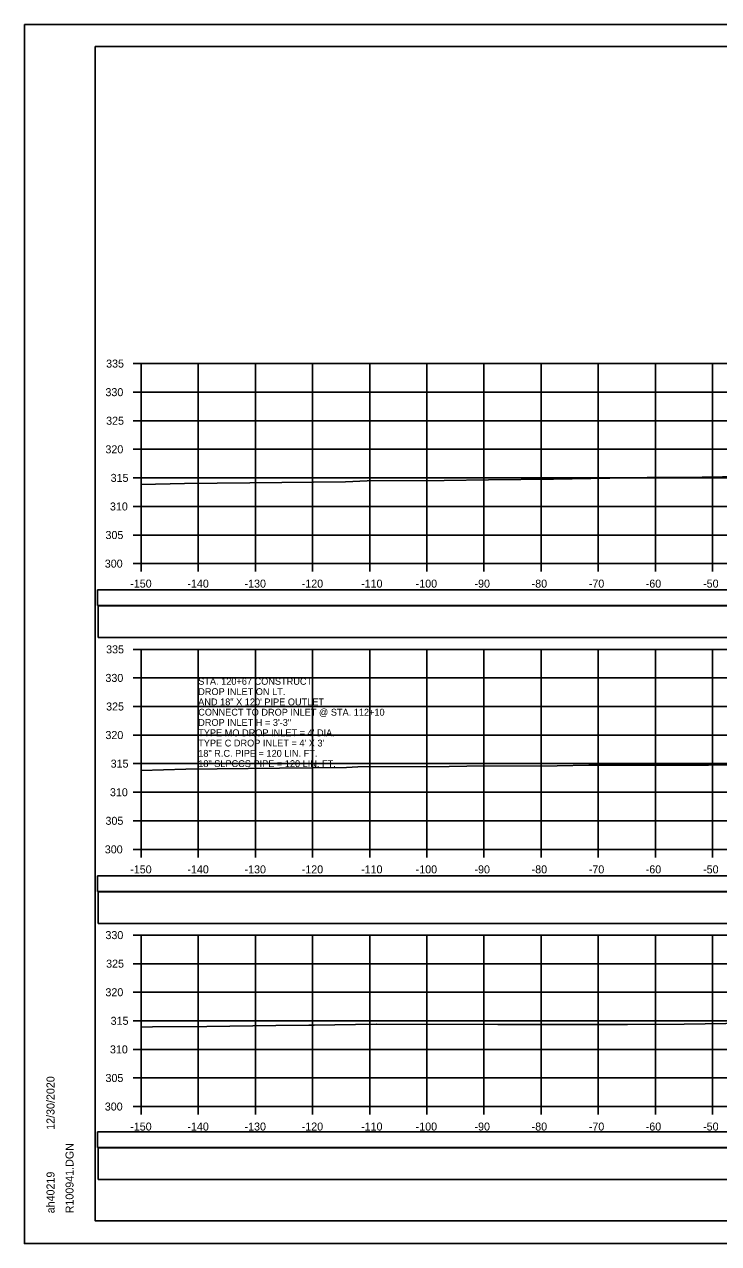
# Model space of a CAD drawing. Extents: x 1370538 to 1372872, y 376220 to 381127.
# Drawn here: x 1371871.6 to 1371993, y 380258.4 to 380471.7 of the extents above; entities that cross this region are included whole.
import ezdxf

# ---------------------------------------------------------------- set-up
doc = ezdxf.new("R2010")
doc.units = 0
for name, color, linetype in [('R_Border Notes', 7, 'Continuous'), ('R_Border PE', 7, 'Continuous'), ('R_Border Prem', 7, 'Continuous'), ('R_Dimension', 7, 'Continuous'), ('R_Fin Surface', 7, 'Continuous'), ('R_Grid', 7, 'Continuous'), ('R_No Plot', 7, 'Continuous'), ('R_Water Annot', 7, 'Continuous'), ('T_Detection Zones', 7, 'Continuous')]:
    doc.layers.add(name, color=color, linetype=linetype)

msp = doc.modelspace()

# ---------------------------------------------------------------- linework, layer by layer
at = {"layer": 'R_Border Notes'}
for p, q in [((1371883.97, 380467.83), (1372200.15, 380467.83)), ((1371883.97, 380262.37), (1371883.97, 380467.83)), ((1371883.97, 380262.37), (1371883.97, 380262.37)), ((1372200.15, 380262.37), (1371883.97, 380262.37))]:
    msp.add_line(p, q, dxfattribs=at)
at = {"layer": 'R_Border Prem'}
for p, q in [((1371890.57, 380412.37), (1371891.97, 380412.37)), ((1371891.97, 380377.37), (1371891.97, 380412.37)), ((1371890.57, 380407.37), (1371891.97, 380407.37)), ((1371890.57, 380402.37), (1371891.97, 380402.37)), ((1371890.57, 380397.37), (1371891.97, 380397.37)), ((1371890.57, 380392.37), (1371891.97, 380392.37)), ((1371890.57, 380387.37), (1371891.97, 380387.37)), ((1371890.57, 380382.37), (1371891.97, 380382.37)), ((1371890.57, 380377.37), (1371891.97, 380377.37)), ((1371891.97, 380377.37), (1372191.97, 380377.37)), ((1371891.97, 380375.97), (1371891.97, 380377.37)), ((1371901.97, 380375.97), (1371901.97, 380377.37)), ((1371911.97, 380375.97), (1371911.97, 380377.37)), ((1371921.97, 380375.97), (1371921.97, 380377.37)), ((1371931.97, 380375.97), (1371931.97, 380377.37)), ((1371941.97, 380375.97), (1371941.97, 380377.37)), ((1371951.97, 380375.97), (1371951.97, 380377.37)), ((1371961.97, 380375.97), (1371961.97, 380377.37)), ((1371971.97, 380375.97), (1371971.97, 380377.37)), ((1371981.97, 380375.97), (1371981.97, 380377.37)), ((1371991.97, 380375.97), (1371991.97, 380377.37)), ((1371890.57, 380362.37), (1371891.97, 380362.37)), ((1371891.97, 380327.37), (1371891.97, 380362.37)), ((1371890.57, 380357.37), (1371891.97, 380357.37)), ((1371890.57, 380352.37), (1371891.97, 380352.37)), ((1371890.57, 380347.37), (1371891.97, 380347.37)), ((1371890.57, 380342.37), (1371891.97, 380342.37)), ((1371890.57, 380337.37), (1371891.97, 380337.37)), ((1371890.57, 380332.37), (1371891.97, 380332.37)), ((1371890.57, 380327.37), (1371891.97, 380327.37)), ((1371891.97, 380327.37), (1372191.97, 380327.37)), ((1371891.97, 380325.97), (1371891.97, 380327.37)), ((1371901.97, 380325.97), (1371901.97, 380327.37)), ((1371911.97, 380325.97), (1371911.97, 380327.37)), ((1371921.97, 380325.97), (1371921.97, 380327.37)), ((1371931.97, 380325.97), (1371931.97, 380327.37)), ((1371941.97, 380325.97), (1371941.97, 380327.37)), ((1371951.97, 380325.97), (1371951.97, 380327.37)), ((1371961.97, 380325.97), (1371961.97, 380327.37)), ((1371971.97, 380325.97), (1371971.97, 380327.37)), ((1371981.97, 380325.97), (1371981.97, 380327.37)), ((1371991.97, 380325.97), (1371991.97, 380327.37)), ((1371890.57, 380312.37), (1371891.97, 380312.37)), ((1371891.97, 380282.37), (1371891.97, 380312.37)), ((1371890.57, 380307.37), (1371891.97, 380307.37)), ((1371890.57, 380302.37), (1371891.97, 380302.37)), ((1371890.57, 380297.37), (1371891.97, 380297.37)), ((1371890.57, 380292.37), (1371891.97, 380292.37)), ((1371890.57, 380287.37), (1371891.97, 380287.37)), ((1371890.57, 380282.37), (1371891.97, 380282.37)), ((1371891.97, 380282.37), (1372191.97, 380282.37)), ((1371891.97, 380280.97), (1371891.97, 380282.37)), ((1371901.97, 380280.97), (1371901.97, 380282.37)), ((1371911.97, 380280.97), (1371911.97, 380282.37)), ((1371921.97, 380280.97), (1371921.97, 380282.37)), ((1371931.97, 380280.97), (1371931.97, 380282.37)), ((1371941.97, 380280.97), (1371941.97, 380282.37)), ((1371951.97, 380280.97), (1371951.97, 380282.37)), ((1371961.97, 380280.97), (1371961.97, 380282.37)), ((1371971.97, 380280.97), (1371971.97, 380282.37)), ((1371981.97, 380280.97), (1371981.97, 380282.37)), ((1371991.97, 380280.97), (1371991.97, 380282.37))]:
    msp.add_line(p, q, dxfattribs=at)
at = {"layer": 'R_Dimension'}
for points in [[(1371891.97, 380391.19), (1371899.58, 380391.4), (1371911.02, 380391.52), (1371927.76, 380391.7), (1371931.54, 380391.84), (1371945.03, 380391.91), (1371952.77, 380392.04), (1371964.11, 380392.12), (1371980.5, 380392.43), (1371985.29, 380392.43), (1371986.59, 380392.43), (1372000.75, 380392.65)], [(1371891.97, 380341.19), (1371899.79, 380341.41), (1371916.18, 380341.58), (1371927.92, 380341.72), (1371929.91, 380341.79), (1371945.86, 380341.86), (1371948.97, 380341.91), (1371964.78, 380341.99), (1371970.33, 380342.08), (1371979.56, 380342.1), (1371986.59, 380342.11), (1371991.28, 380342.11), (1371995.62, 380342.19)], [(1371891.97, 380296.27), (1371893.95, 380296.33), (1371903.47, 380296.39), (1371915.55, 380296.54), (1371921.3, 380296.61), (1371922.24, 380296.61), (1371933.1, 380296.76), (1371933.12, 380296.76), (1371933.16, 380296.76), (1371954.4, 380296.75), (1371963.68, 380296.73), (1371970.39, 380296.75), (1371977.1, 380296.75), (1371987.01, 380296.78), (1372005.27, 380297.05)]]:
    msp.add_lwpolyline(points, dxfattribs=at)
at = {"layer": 'R_Fin Surface'}
for points in [[(1371884.44, 380364.44), (1372199.45, 380364.44), (1372199.45, 380370), (1371884.44, 380370)], [(1371884.44, 380314.39), (1372199.45, 380314.39), (1372199.45, 380319.95), (1371884.44, 380319.95)], [(1371884.44, 380269.6), (1372199.45, 380269.6), (1372199.45, 380275.17), (1371884.44, 380275.17)]]:
    msp.add_lwpolyline(points, close=True, dxfattribs=at)
at = {"layer": 'R_Grid'}
for p, q in [((1371891.97, 380412.37), (1372191.97, 380412.37)), ((1371891.97, 380377.37), (1371891.97, 380412.37)), ((1371901.97, 380377.37), (1371901.97, 380412.37)), ((1371911.97, 380377.37), (1371911.97, 380412.37)), ((1371921.97, 380377.37), (1371921.97, 380412.37)), ((1371931.97, 380377.37), (1371931.97, 380412.37)), ((1371941.97, 380377.37), (1371941.97, 380412.37)), ((1371951.97, 380377.37), (1371951.97, 380412.37)), ((1371961.97, 380377.37), (1371961.97, 380412.37)), ((1371971.97, 380377.37), (1371971.97, 380412.37)), ((1371981.97, 380377.37), (1371981.97, 380412.37)), ((1371991.97, 380377.37), (1371991.97, 380412.37)), ((1371891.97, 380407.37), (1372191.97, 380407.37)), ((1371891.97, 380402.37), (1372191.97, 380402.37)), ((1371891.97, 380397.37), (1372191.97, 380397.37)), ((1371891.97, 380392.37), (1372191.97, 380392.37)), ((1371891.97, 380387.37), (1372191.97, 380387.37)), ((1371891.97, 380382.37), (1372191.97, 380382.37)), ((1371891.97, 380377.37), (1372191.97, 380377.37)), ((1371891.97, 380362.37), (1372191.97, 380362.37)), ((1371891.97, 380327.37), (1371891.97, 380362.37)), ((1371901.97, 380327.37), (1371901.97, 380362.37)), ((1371911.97, 380327.37), (1371911.97, 380362.37)), ((1371921.97, 380327.37), (1371921.97, 380362.37)), ((1371931.97, 380327.37), (1371931.97, 380362.37)), ((1371941.97, 380327.37), (1371941.97, 380362.37)), ((1371951.97, 380327.37), (1371951.97, 380362.37)), ((1371961.97, 380327.37), (1371961.97, 380362.37)), ((1371971.97, 380327.37), (1371971.97, 380362.37)), ((1371981.97, 380327.37), (1371981.97, 380362.37)), ((1371991.97, 380327.37), (1371991.97, 380362.37)), ((1371891.97, 380357.37), (1372191.97, 380357.37)), ((1371891.97, 380352.37), (1372191.97, 380352.37)), ((1371891.97, 380347.37), (1372191.97, 380347.37)), ((1371891.97, 380342.37), (1372191.97, 380342.37)), ((1371891.97, 380337.37), (1372191.97, 380337.37)), ((1371891.97, 380332.37), (1372191.97, 380332.37)), ((1371891.97, 380327.37), (1372191.97, 380327.37)), ((1371891.97, 380312.37), (1372191.97, 380312.37)), ((1371891.97, 380282.37), (1371891.97, 380312.37)), ((1371901.97, 380282.37), (1371901.97, 380312.37)), ((1371911.97, 380282.37), (1371911.97, 380312.37)), ((1371921.97, 380282.37), (1371921.97, 380312.37)), ((1371931.97, 380282.37), (1371931.97, 380312.37)), ((1371941.97, 380282.37), (1371941.97, 380312.37)), ((1371951.97, 380282.37), (1371951.97, 380312.37)), ((1371961.97, 380282.37), (1371961.97, 380312.37)), ((1371971.97, 380282.37), (1371971.97, 380312.37)), ((1371981.97, 380282.37), (1371981.97, 380312.37)), ((1371991.97, 380282.37), (1371991.97, 380312.37)), ((1371891.97, 380307.37), (1372191.97, 380307.37)), ((1371891.97, 380302.37), (1372191.97, 380302.37)), ((1371891.97, 380297.37), (1372191.97, 380297.37)), ((1371891.97, 380292.37), (1372191.97, 380292.37)), ((1371891.97, 380287.37), (1372191.97, 380287.37)), ((1371891.97, 380282.37), (1372191.97, 380282.37))]:
    msp.add_line(p, q, dxfattribs=at)
at = {"layer": 'R_No Plot'}
for p, q in [((1371871.57, 380471.72), (1372204.9, 380471.72)), ((1371871.57, 380258.39), (1372204.9, 380258.39))]:
    msp.add_line(p, q, dxfattribs=at)
for points in [[(1371871.56, 380471.72), (1372204.9, 380471.72), (1372204.9, 380258.39), (1371871.56, 380258.39)], [(1372117.89, 380467.83), (1372117.89, 380457.95), (1372153.62, 380457.95), (1372153.62, 380455.03), (1372176.82, 380455.03), (1372176.82, 380430.7), (1372200.15, 380430.7), (1372200.15, 380262.37), (1371883.97, 380262.37), (1371883.97, 380467.83)]]:
    msp.add_lwpolyline(points, close=True, dxfattribs=at)
at = {"layer": 'T_Detection Zones'}
for points in [[(1371884.38, 380370.06), (1372199.5, 380370.06), (1372199.5, 380372.77), (1371884.38, 380372.77)], [(1371884.38, 380320.01), (1372199.5, 380320.01), (1372199.5, 380322.72), (1371884.38, 380322.72)], [(1371884.38, 380275.22), (1372199.5, 380275.22), (1372199.5, 380277.93), (1371884.38, 380277.93)]]:
    msp.add_lwpolyline(points, close=True, dxfattribs=at)

# ---------------------------------------------------------------- texts
at = {"layer": 'R_Border Notes'}
for s, p in [('12/30/2020', (1371876.83, 380278.3)), ('R100941.DGN', (1371880.16, 380263.69)), ('ah40219', (1371876.83, 380263.69))]:
    msp.add_text(s, height=1.4, rotation=90, dxfattribs=at).set_placement(p)
at = {"layer": 'R_Border PE'}
for s, p in [('335', (1371885.86, 380411.67)), ('330', (1371885.74, 380406.67)), ('325', (1371885.86, 380401.67)), ('320', (1371885.74, 380396.67)), ('315', (1371886.65, 380391.67)), ('310', (1371886.53, 380386.67)), ('305', (1371885.75, 380381.67)), ('300', (1371885.63, 380376.67)), ('-150', (1371890.08, 380373.17)), ('-140', (1371900.08, 380373.17)), ('-130', (1371910.08, 380373.17)), ('-120', (1371920.08, 380373.17)), ('-110', (1371930.47, 380373.17)), ('-100', (1371940.02, 380373.17)), ('-90', (1371950.31, 380373.17)), ('-80', (1371960.31, 380373.17)), ('-70', (1371970.31, 380373.17)), ('-60', (1371980.27, 380373.17)), ('-50', (1371990.31, 380373.17)), ('335', (1371885.86, 380361.67)), ('330', (1371885.74, 380356.67)), ('325', (1371885.86, 380351.67)), ('320', (1371885.74, 380346.67)), ('315', (1371886.65, 380341.67)), ('310', (1371886.53, 380336.67)), ('305', (1371885.75, 380331.67)), ('300', (1371885.63, 380326.67)), ('-150', (1371890.08, 380323.17)), ('-140', (1371900.08, 380323.17)), ('-130', (1371910.08, 380323.17)), ('-120', (1371920.08, 380323.17)), ('-110', (1371930.47, 380323.17)), ('-100', (1371940.02, 380323.17)), ('-90', (1371950.31, 380323.17)), ('-80', (1371960.31, 380323.17)), ('-70', (1371970.31, 380323.17)), ('-60', (1371980.27, 380323.17)), ('-50', (1371990.31, 380323.17)), ('330', (1371885.74, 380311.67)), ('325', (1371885.86, 380306.67)), ('320', (1371885.74, 380301.67)), ('315', (1371886.65, 380296.67)), ('310', (1371886.53, 380291.67)), ('305', (1371885.75, 380286.67)), ('300', (1371885.63, 380281.67)), ('-150', (1371890.08, 380278.17)), ('-140', (1371900.08, 380278.17)), ('-130', (1371910.08, 380278.17)), ('-120', (1371920.08, 380278.17)), ('-110', (1371930.47, 380278.17)), ('-100', (1371940.02, 380278.17)), ('-90', (1371950.31, 380278.17)), ('-80', (1371960.31, 380278.17)), ('-70', (1371970.31, 380278.17)), ('-60', (1371980.27, 380278.17)), ('-50', (1371990.31, 380278.17))]:
    msp.add_text(s, height=1.4, dxfattribs=at).set_placement(p)
at = {"layer": 'R_Water Annot'}
for s, p in [('STA. 120+67 CONSTRUCT', (1371901.97, 380356.17)), ('DROP INLET ON LT.', (1371901.97, 380354.37)), ('AND 18" X 120\' PIPE OUTLET', (1371901.97, 380352.57)), ('CONNECT TO DROP INLET @ STA. 112+10', (1371901.97, 380350.77)), ('DROP INLET H = 3\'-3"', (1371901.97, 380348.97)), ("TYPE MO DROP INLET = 4' DIA.", (1371901.97, 380347.17)), ("TYPE C DROP INLET = 4' X 3'", (1371901.97, 380345.37)), ('18" R.C. PIPE = 120 LIN. FT.', (1371901.97, 380343.57)), ('18" SLPCCS PIPE = 120 LIN. FT.', (1371901.97, 380341.77))]:
    msp.add_text(s, height=1.2, dxfattribs=at).set_placement(p)

doc.saveas('drawing.dxf')
